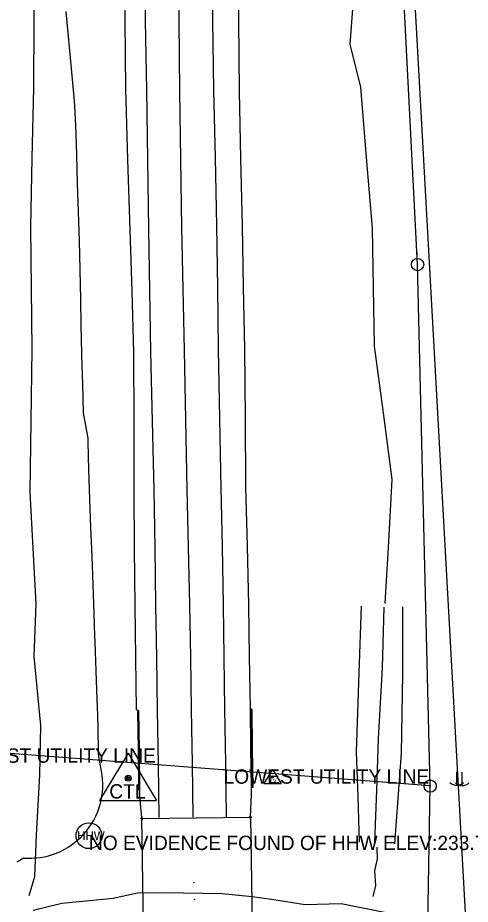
# Model space of a CAD drawing. Extents: x 1674300 to 1677920, y 225056 to 231852.
# Drawn here: x 1677397.9 to 1677555.6, y 229147 to 229456.1 of the extents above; entities that cross this region are included whole.
import ezdxf

# ---------------------------------------------------------------- set-up
doc = ezdxf.new("R2010")
doc.units = 0
for name, color, linetype in [('R_Proposed Const Limits_Cut', 7, 'Continuous'), ('R_Proposed Const Limits_Fill', 7, 'Continuous'), ('S_BRIDGE', 7, 'Continuous'), ('S_DITCHLINE', 7, 'Continuous'), ('S_EDGE_CONCRETE', 7, 'Continuous'), ('S_EDGE_PAVEMENT', 7, 'Continuous'), ('S_ELECTRIC_UTILITIES', 7, 'Continuous'), ('S_ELECTRIC_UTILITIES_ANNOT', 7, 'Continuous'), ('S_EXIST_ROW', 7, 'Continuous'), ('S_HIST_HIGH_WATER', 7, 'Continuous'), ('S_HIST_HIGH_WATER_ANNOT', 7, 'Continuous'), ('S_MSC_PT_SYM', 7, 'Continuous'), ('S_PAVEMENT_CROWN', 7, 'Continuous'), ('S_PRIMARY_CTL', 7, 'Continuous'), ('S_SECONDARY_CTL', 7, 'Continuous'), ('S_SHOULDER', 7, 'Continuous'), ('S_STR_PT_SYM', 7, 'Continuous'), ('S_STREAM', 7, 'Continuous'), ('S_UTILITY_POLE', 7, 'Continuous'), ('S_UTL_PT_SYM', 7, 'Continuous')]:
    doc.layers.add(name, color=color, linetype=linetype)

msp = doc.modelspace()

# ---------------------------------------------------------------- linework, layer by layer
at = {"layer": 'R_Proposed Const Limits_Cut'}
msp.add_lwpolyline([(1677399.84, 229163.15), (1677399.82, 229163.08), (1677399.7, 229163.01), (1677399.52, 229162.89), (1677398.65, 229162.34), (1677398.56, 229162.29), (1677398.42, 229162.19), (1677397.61, 229161.68)], dxfattribs=at)
at = {"layer": 'R_Proposed Const Limits_Fill'}
msp.add_lwpolyline([(1677427.06, 229193.49), (1677426.1, 229198.48), (1677426.07, 229200.03), (1677425.88, 229208.48), (1677425.77, 229213.02), (1677425.59, 229218.47), (1677425.21, 229228.47), (1677424.82, 229238.46), (1677424.74, 229240.61), (1677424.46, 229248.46), (1677424.12, 229258.46), (1677423.77, 229268.45), (1677423.38, 229278.45), (1677423, 229288.44), (1677422.7, 229298.44), (1677422.46, 229308.44), (1677422.43, 229309.58), (1677420.8, 229318.41), (1677420.55, 229328.41), (1677420.26, 229338.41), (1677420.12, 229344.48), (1677420.04, 229348.41), (1677419.83, 229358.4), (1677419.72, 229362.86), (1677419.59, 229368.4), (1677419.35, 229378.4), (1677419.06, 229388.4), (1677418.76, 229398.39), (1677418.44, 229408.39), (1677418.2, 229415.54), (1677418.09, 229418.39), (1677417.83, 229425.53), (1677417.58, 229428.38), (1677416.65, 229438.37), (1677415.72, 229448.36), (1677414.81, 229458.34)], dxfattribs=at)
msp.add_arc((1677401.9, 229188.68), 25.61, 265.3798, 10.8242, dxfattribs=at)
at = {"layer": 'S_BRIDGE'}
for p, q in [((1677441.12, 229176.97), (1677478.98, 229177.38)), ((1677441.95, 229122.22), (1677441.12, 229176.97)), ((1677478.98, 229177.38), (1677479.86, 229122.68))]:
    msp.add_line(p, q, dxfattribs=at)
at = {"layer": 'S_DITCHLINE'}
for points in [[(1677401.81, 229150.07), (1677403.83, 229156.72), (1677404.42, 229171.13), (1677405.53, 229192.17), (1677405.88, 229209.42), (1677403.57, 229233.42), (1677404.29, 229251.75), (1677403.25, 229271.24), (1677402.21, 229290.73), (1677402.54, 229315.6), (1677402.86, 229340.46), (1677402.63, 229361.7), (1677402.41, 229382.95), (1677402.96, 229407.28), (1677403.51, 229431.62), (1677403.55, 229454.93), (1677403.6, 229478.23)], [(1677526.01, 229251.88), (1677527.22, 229273.51), (1677528.43, 229295.14), (1677525.35, 229318.39), (1677522.27, 229341.64), (1677521.88, 229362.2), (1677521.5, 229382.77), (1677519.49, 229407.37), (1677517.49, 229431.97), (1677513.78, 229446.92), (1677515.05, 229463.87)], [(1677525.45, 229250.61), (1677524.91, 229229.46), (1677523.57, 229204.88), (1677522.91, 229186.82), (1677522.26, 229168.76)]]:
    msp.add_lwpolyline(points, dxfattribs=at)
at = {"layer": 'S_EDGE_CONCRETE'}
for points in [[(1677517.07, 229168.73), (1677516.5, 229184.46), (1677515.92, 229200.19), (1677516.43, 229213.95), (1677516.93, 229227.7), (1677517.71, 229250.95)], [(1677529.33, 229168.07), (1677530.51, 229183.92), (1677531.7, 229199.76), (1677531.88, 229213.54), (1677532.07, 229227.32), (1677532.16, 229250.74)]]:
    msp.add_lwpolyline(points, dxfattribs=at)
for points in [[(1677439.61, 229214.28), (1677439.8, 229200.76), (1677439.99, 229187.23), (1677440.28, 229187.2), (1677440.08, 229200.79), (1677439.88, 229214.37)], [(1677479.45, 229215.12), (1677479.64, 229201.42), (1677479.83, 229187.73), (1677479.6, 229187.71), (1677479.42, 229201.44), (1677479.25, 229215.18)]]:
    msp.add_lwpolyline(points, close=True, dxfattribs=at)
at = {"layer": 'S_EDGE_PAVEMENT'}
for points in [[(1677447.19, 229177.27), (1677446.89, 229195.92), (1677446.59, 229214.57), (1677446.32, 229232.94), (1677446.04, 229251.31), (1677445.77, 229271.34), (1677445.49, 229291.37), (1677444.87, 229315.49), (1677444.24, 229339.62), (1677443.88, 229360.99), (1677443.52, 229382.36), (1677443.19, 229406.6), (1677442.86, 229430.84), (1677442.45, 229455.05), (1677442.04, 229479.26)], [(1677470.66, 229177.52), (1677470.39, 229196.28), (1677470.12, 229215.03), (1677469.88, 229233.21), (1677469.64, 229251.38), (1677469.24, 229271.73), (1677468.83, 229292.08), (1677468.37, 229316.34), (1677467.91, 229340.59), (1677467.59, 229362.11), (1677467.27, 229383.62), (1677466.77, 229407.23), (1677466.27, 229430.84), (1677465.93, 229455.12), (1677465.6, 229479.4)]]:
    msp.add_lwpolyline(points, dxfattribs=at)
at = {"layer": 'S_ELECTRIC_UTILITIES'}
for p, q in [((1677537.26, 229370.07), (1677525.77, 229595.69)), ((1677541.67, 229188.26), (1677537.26, 229370.07)), ((1677541.68, 229188.35), (1677278.13, 229208.63)), ((1677537.01, 228935.14), (1677541.67, 229188.26))]:
    msp.add_line(p, q, dxfattribs=at)
at = {"layer": 'S_EXIST_ROW'}
msp.add_line((1677555.5, 229117.02), (1677521.25, 229735.57), dxfattribs=at)
at = {"layer": 'S_HIST_HIGH_WATER'}
msp.add_circle((1677422.69, 229170.95), 4.5, dxfattribs=at)
at = {"layer": 'S_MSC_PT_SYM'}
for points in [[(1677469.62, 229194.08), (1677469.62, 229194.13), (1677469.62, 229194.08), (1677469.57, 229194.08), (1677469.62, 229194.08), (1677469.62, 229194.03), (1677469.62, 229194.08), (1677469.67, 229194.08)], [(1677459.3, 229154.61), (1677459.3, 229154.66), (1677459.3, 229154.61), (1677459.25, 229154.61), (1677459.3, 229154.61), (1677459.3, 229154.56), (1677459.3, 229154.61), (1677459.35, 229154.61)], [(1677459.27, 229153.01), (1677459.27, 229153.06), (1677459.27, 229153.01), (1677459.22, 229153.01), (1677459.27, 229153.01), (1677459.27, 229152.96), (1677459.27, 229153.01), (1677459.32, 229153.01)], [(1677459.52, 229148.81), (1677459.52, 229148.86), (1677459.52, 229148.81), (1677459.47, 229148.81), (1677459.52, 229148.81), (1677459.52, 229148.76), (1677459.52, 229148.81), (1677459.57, 229148.81)]]:
    msp.add_lwpolyline(points, dxfattribs=at)
at = {"layer": 'S_PAVEMENT_CROWN'}
msp.add_lwpolyline([(1677459.03, 229177.41), (1677458.76, 229196.1), (1677458.49, 229214.8), (1677458.18, 229233.1), (1677457.86, 229251.4), (1677457.39, 229271.52), (1677456.91, 229291.64), (1677456.47, 229315.95), (1677456.03, 229340.26), (1677455.53, 229361.57), (1677455.03, 229382.88), (1677454.71, 229406.68), (1677454.39, 229430.48), (1677454.11, 229454.96), (1677453.84, 229479.45)], dxfattribs=at)
at = {"layer": 'S_PRIMARY_CTL'}
for p, q in [((1677436.38, 229199.68), (1677426.35, 229183.17)), ((1677436.38, 229199.68), (1677446.2, 229183.17)), ((1677426.35, 229183.17), (1677446.2, 229183.17))]:
    msp.add_line(p, q, dxfattribs=at)
for radius in [1.04, 0.609, 0.344]:
    msp.add_circle((1677436.38, 229190.98), radius, dxfattribs=at)
at = {"layer": 'S_SECONDARY_CTL'}
for p, q in [((1677486.71, 229194.07), (1677483.7, 229189.11)), ((1677486.71, 229194.07), (1677489.66, 229189.11)), ((1677483.7, 229189.11), (1677489.66, 229189.11))]:
    msp.add_line(p, q, dxfattribs=at)
for radius in [0.311, 0.183, 0.103]:
    msp.add_circle((1677486.71, 229191.46), radius, dxfattribs=at)
at = {"layer": 'S_SHOULDER'}
for points in [[(1677440.09, 229214.52), (1677439.33, 229214.78), (1677439.05, 229232.96), (1677438.77, 229251.14), (1677438.61, 229271.03), (1677438.45, 229290.93), (1677438.42, 229315.16), (1677438.38, 229339.39), (1677437.73, 229360.81), (1677437.09, 229382.22), (1677436.3, 229406.69), (1677435.52, 229431.17), (1677435.32, 229455.13), (1677435.12, 229479.1)], [(1677479.01, 229215.37), (1677478.71, 229233.34), (1677478.41, 229251.31), (1677477.93, 229271.97), (1677477.44, 229292.63), (1677477.23, 229316.68), (1677477.02, 229340.72), (1677476.63, 229362.16), (1677476.23, 229383.6), (1677475.68, 229407.08), (1677475.14, 229430.56), (1677474.9, 229455.1), (1677474.67, 229479.64)], [(1677441.13, 229177.25), (1677440.48, 229184.47), (1677440.48, 229187.18), (1677440.28, 229200.83), (1677440.08, 229214.48)], [(1677479, 229177.6), (1677479.4, 229185.05), (1677479.36, 229187.71), (1677479.19, 229201.54), (1677479.02, 229215.37)]]:
    msp.add_lwpolyline(points, dxfattribs=at)
at = {"layer": 'S_STR_PT_SYM'}
for points in [[(1677441.12, 229176.97), (1677441.12, 229177.47), (1677441.12, 229176.97), (1677440.62, 229176.97), (1677441.12, 229176.97), (1677441.12, 229176.47), (1677441.12, 229176.97), (1677441.62, 229176.97)], [(1677478.98, 229177.38), (1677478.98, 229177.88), (1677478.98, 229177.38), (1677478.48, 229177.38), (1677478.98, 229177.38), (1677478.98, 229176.88), (1677478.98, 229177.38), (1677479.48, 229177.38)]]:
    msp.add_lwpolyline(points, dxfattribs=at)
at = {"layer": 'S_STREAM'}
for points in [[(1677523.11, 229166.98), (1677523.18, 229162.94), (1677522.26, 229158.65), (1677522.58, 229153.61), (1677521.72, 229149.78)], [(1677527.43, 229143.82), (1677510.66, 229147.15), (1677498.12, 229146.82), (1677486.33, 229148.7), (1677479.59, 229149.67), (1677469.13, 229150.63), (1677448.9, 229150.99), (1677439.66, 229150.9), (1677431.13, 229149.09), (1677421.74, 229148.09), (1677413.29, 229147.37), (1677403.31, 229144.91)]]:
    msp.add_lwpolyline(points, dxfattribs=at)
at = {"layer": 'S_UTILITY_POLE'}
for p, q in [((1677537.13, 229372.21), (1677537.13, 229374.32)), ((1677541.54, 229190.4), (1677541.54, 229192.51)), ((1677550.83, 229193.23), (1677550.83, 229188.5)), ((1677552.73, 229193.13), (1677552.73, 229188.41))]:
    msp.add_line(p, q, dxfattribs=at)
for centre in [(1677537.26, 229370.07), (1677541.67, 229188.26)]:
    msp.add_circle(centre, 2.13, dxfattribs=at)
for centre in [(1677550.89, 229191.93), (1677552.79, 229191.83)]:
    msp.add_arc(centre, 3.41, 226.3972, 313.6028, dxfattribs=at)
at = {"layer": 'S_UTL_PT_SYM'}
for points in [[(1677537.26, 229370.07), (1677537.26, 229370.12), (1677537.26, 229370.07), (1677537.21, 229370.07), (1677537.26, 229370.07), (1677537.26, 229370.02), (1677537.26, 229370.07), (1677537.31, 229370.07)], [(1677469.62, 229194.08), (1677469.62, 229194.13), (1677469.62, 229194.08), (1677469.57, 229194.08), (1677469.62, 229194.08), (1677469.62, 229194.03), (1677469.62, 229194.08), (1677469.67, 229194.08)], [(1677541.67, 229188.26), (1677541.67, 229188.31), (1677541.67, 229188.26), (1677541.62, 229188.26), (1677541.67, 229188.26), (1677541.67, 229188.21), (1677541.67, 229188.26), (1677541.72, 229188.26)], [(1677541.68, 229188.35), (1677541.68, 229188.4), (1677541.68, 229188.35), (1677541.63, 229188.35), (1677541.68, 229188.35), (1677541.68, 229188.3), (1677541.68, 229188.35), (1677541.73, 229188.35)]]:
    msp.add_lwpolyline(points, dxfattribs=at)

# ---------------------------------------------------------------- texts
at = {"layer": 'S_ELECTRIC_UTILITIES_ANNOT'}
for p in [(1677374.33, 229196.39), (1677469.62, 229189.08)]:
    msp.add_text('LOWEST UTILITY LINE', height=5, dxfattribs=at).set_placement(p)
at = {"layer": 'S_HIST_HIGH_WATER'}
msp.add_text('HHW', height=3, rotation=360, dxfattribs=at).set_placement((1677418.6, 229169.45))
at = {"layer": 'S_HIST_HIGH_WATER_ANNOT'}
msp.add_text('NO EVIDENCE FOUND OF HHW ELEV:233.79', height=5, dxfattribs=at).set_placement((1677422.69, 229165.95))
at = {"layer": 'S_PRIMARY_CTL'}
msp.add_text('CTL', height=5, rotation=360, dxfattribs=at).set_placement((1677429.79, 229183.91))
at = {"layer": 'S_SECONDARY_CTL'}
msp.add_text('TV', height=1.5, rotation=360, dxfattribs=at).set_placement((1677485.51, 229189.45))

doc.saveas('drawing.dxf')
